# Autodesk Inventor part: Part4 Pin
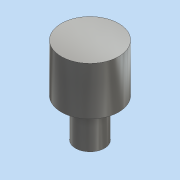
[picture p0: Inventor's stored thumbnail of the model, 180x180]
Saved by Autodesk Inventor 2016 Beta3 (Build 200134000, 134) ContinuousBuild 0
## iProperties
Created: 2015-11
Part Number: Part4 Pin
Material: Aluminum 6061-AHC
Document SubType Name: Modeling
Designer: SanPer86
Density: 2.7 g/cm^3
Appearance: Sky Blue Dark
Mass: 0.000884711 g
Surface Area: 0.0292368 cm^2
Volume: 0.000327671 cm^3
Author: SanPer86
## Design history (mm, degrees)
sketch "Sketch1"
  geometry: C1 r 0.373 at (0, 0); 1 further point
  constraints: 1 centre point
  dimensions: "d8" = 0.745 diameter of C1
extrude "Extrusion1" new body sketch "Sketch1" distance "d9" = 0.625; taper "d10" = 0 deg
sketch "Sketch2"
  geometry: C1 r 0.188 at (0, 0); 1 further point
  constraints: 1 centre point, 1 coincident
  dimensions: "d11" = 0.375 diameter of C1
extrude "Extrusion2" join sketch "Sketch2" distance "d12" = 0.5; taper "d13" = 0 deg
body "Solid2"
